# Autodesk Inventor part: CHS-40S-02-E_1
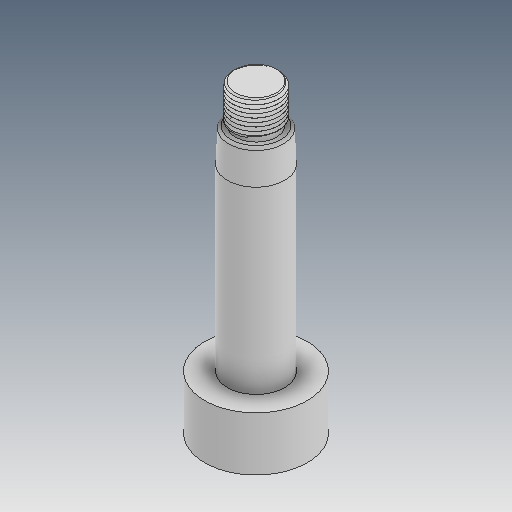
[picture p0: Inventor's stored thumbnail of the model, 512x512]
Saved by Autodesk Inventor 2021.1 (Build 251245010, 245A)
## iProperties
Created: 2019-04
Part Number: CHS-40S-02-E_1
Material: Ogólny
Document SubType Name: Modeling
Designer: user
Density: 1 g/cm^3
Appearance: Domyślna
Author: user
Revision Number: ÈÎºÎ
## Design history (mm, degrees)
feature "ÊäÈë1"
feature "ÊäÈë2"
node "Bryła1"
node "Bryła2"
